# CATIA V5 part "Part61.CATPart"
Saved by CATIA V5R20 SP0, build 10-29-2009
Part number: 9AE103036-4
Revision: ANY
Definition: UNKNOWN
Nomenclature: 9AE103036-4
Source: Unknown
Bounding box of the stored display mesh (mm): x -5.949 to 5.949, y -5.941 to 5.941, z -2.35 to 21.05
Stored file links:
  C:\Users\Utente\Desktop\IO LAVORO\3D X SITO CF\CUMSA\3D files AE\Part61.CATPart
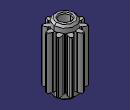
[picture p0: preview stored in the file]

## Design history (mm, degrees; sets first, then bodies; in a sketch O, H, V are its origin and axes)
Body1 "Cortar-Extruir3" (main body)
  Solid1: solid without history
